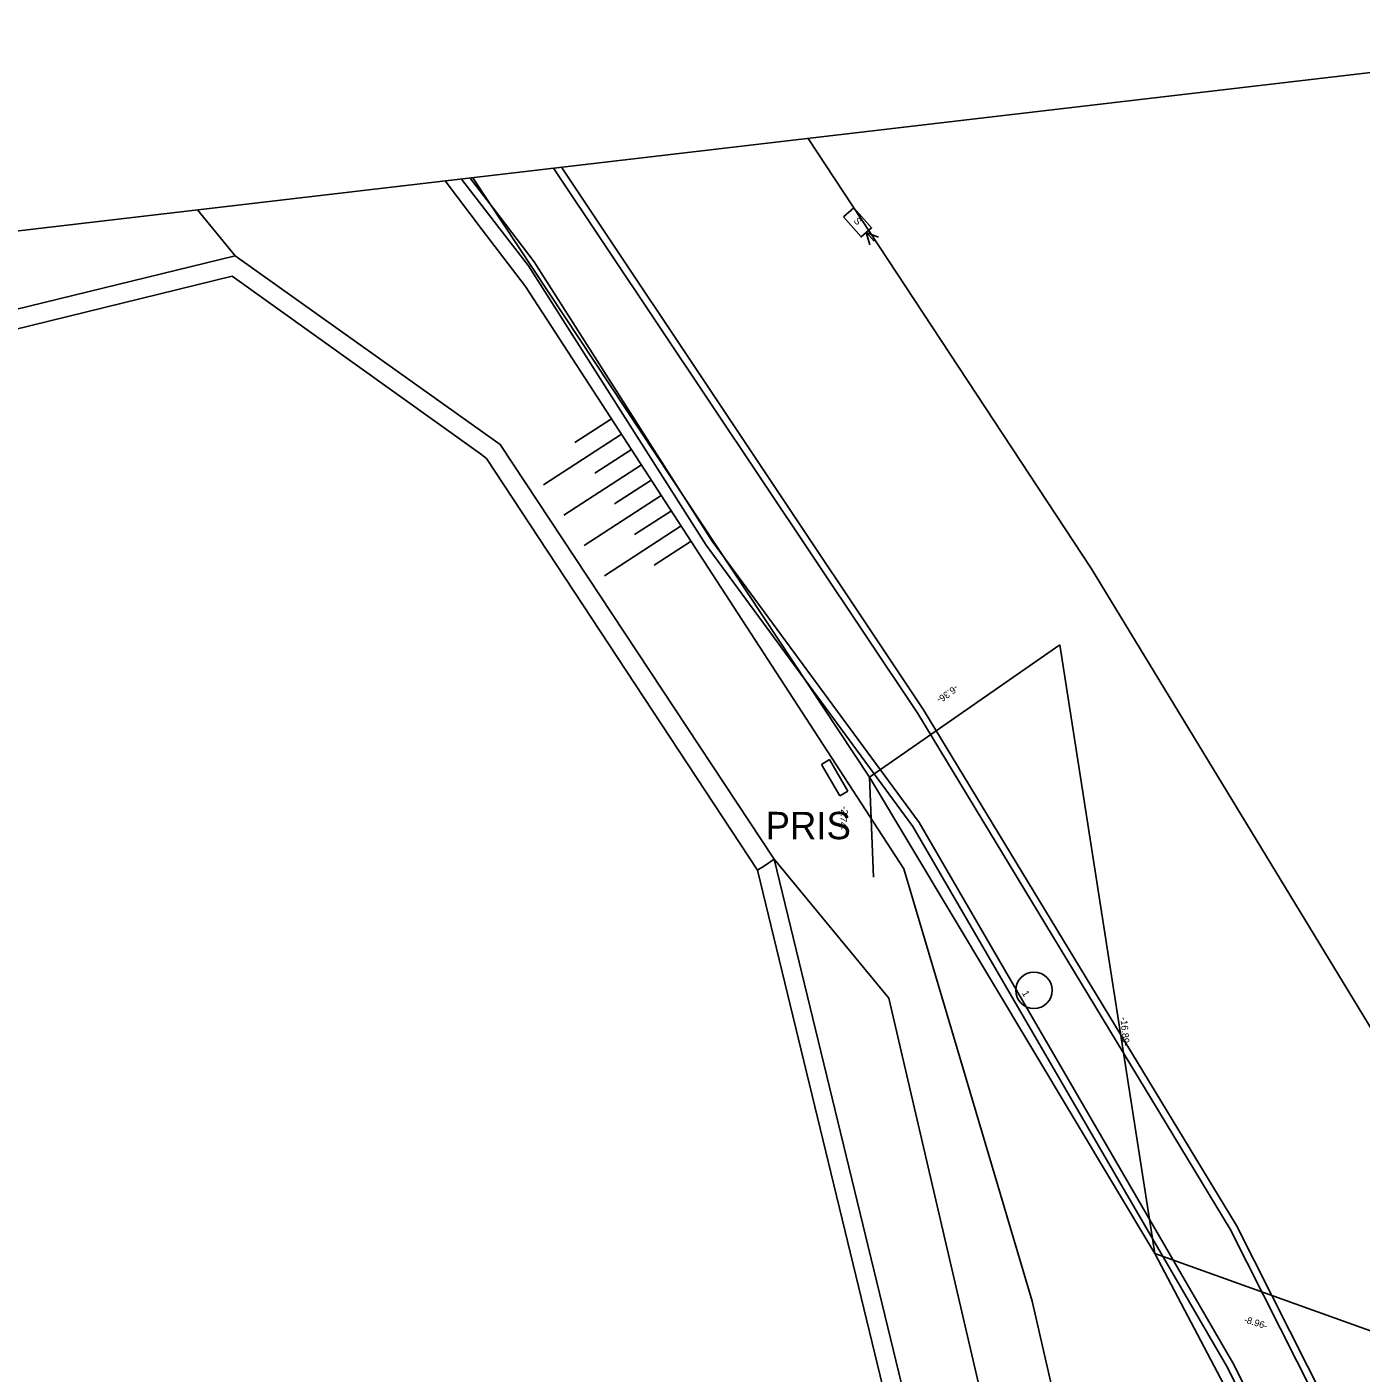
# Model space of a CAD drawing. Extents: x -597791 to -597535, y -1159670 to -1159547.
# Drawn here: x -597726 to -597689.44, y -1159583.4 to -1159546.5 of the extents above; entities that cross this region are included whole.
import ezdxf

# ---------------------------------------------------------------- set-up
doc = ezdxf.new("R2010")
doc.units = 0
for name, color, linetype in [('Koordinační kabel-Pom_KK Metalic', 7, 'Continuous'), ('Koordinační kabel-Pom_Oměrná KKM', 7, 'Continuous'), ('Koordinační kabel-Pom_Text KKM', 7, 'Continuous'), ('MAPA', 7, 'Continuous'), ('Ostatní', 7, 'Continuous'), ('Žádosti', 7, 'Continuous')]:
    doc.layers.add(name, color=color, linetype=linetype)

msp = doc.modelspace()

# ---------------------------------------------------------------- linework, layer by layer
at = {"layer": 'Koordinační kabel-Pom_KK Metalic'}
msp.add_lwpolyline([(-597673.151, -1159662.001), (-597672.53, -1159646.67), (-597673.26, -1159634.82), (-597674.43, -1159629.89), (-597674.64, -1159626.96), (-597676.13, -1159624.16), (-597682.12, -1159607.29), (-597687.7, -1159594.16), (-597695.09, -1159580.13), (-597702.91, -1159567.07), (-597713.779, -1159550.637)], dxfattribs=at)
at = {"layer": 'Koordinační kabel-Pom_Oměrná KKM'}
for points in [[(-597697.69, -1159563.44), (-597702.91, -1159567.07)], [(-597695.09, -1159580.13), (-597697.69, -1159563.44)], [(-597702.91, -1159567.07), (-597702.8, -1159569.81)], [(-597695.09, -1159580.13), (-597686.66, -1159583.15)]]:
    msp.add_lwpolyline(points, dxfattribs=at)
at = {"layer": 'Koordinační kabel-Pom_Text KKM'}
msp.add_circle((-597698.404, -1159572.911), 0.5, dxfattribs=at)
at = {"layer": 'MAPA'}
for p, q in [((-597711.569, -1159550.378), (-597701.59, -1159565.32)), ((-597721.331, -1159551.521), (-597720.29, -1159552.78))]:
    msp.add_line(p, q, dxfattribs=at)
for points in [[(-597704.593, -1159549.561), (-597696.83, -1159561.36), (-597686.72, -1159577.97), (-597680.02, -1159590.93), (-597674.28, -1159604.46), (-597669.36, -1159619.22), (-597665.99, -1159632.8), (-597665.39, -1159635.96)], [(-597711.348, -1159550.352), (-597701.43, -1159565.22), (-597692.85, -1159579.36)], [(-597714.535, -1159550.725), (-597713.521, -1159552.063), (-597712.34, -1159553.62), (-597701.97, -1159569.58), (-597698.45, -1159581.43), (-597695.48, -1159594.37), (-597692.77, -1159605.67), (-597689.38, -1159619.96), (-597686.19, -1159632.52), (-597681.76, -1159634.88), (-597680.28, -1159632.32), (-597675.87, -1159632.46)], [(-597714.094, -1159550.674), (-597713.193, -1159551.841), (-597712.26, -1159553.05), (-597707.39, -1159560.71)], [(-597713.858, -1159550.646), (-597713.03, -1159551.72), (-597712.1, -1159552.94), (-597707.22, -1159560.6)], [(-597757.7, -1159561.95), (-597747.37, -1159559.39), (-597720.29, -1159552.78), (-597713.03, -1159557.95), (-597705.52, -1159569.32)], [(-597758.88, -1159636.94), (-597772.32, -1159583.78), (-597776.69, -1159567.07), (-597747.44, -1159559.98), (-597720.38, -1159553.34), (-597713.57, -1159558.21), (-597713.41, -1159558.33), (-597705.98, -1159569.62)], [(-597710.99, -1159557.9), (-597709.98, -1159557.25)], [(-597711.84, -1159559.06), (-597709.71, -1159557.67)], [(-597710.44, -1159558.74), (-597709.43, -1159558.09)], [(-597711.29, -1159559.89), (-597709.16, -1159558.51)], [(-597709.9, -1159559.58), (-597708.89, -1159558.93)], [(-597710.73, -1159560.72), (-597708.62, -1159559.35)], [(-597709.35, -1159560.42), (-597708.34, -1159559.77)], [(-597710.17, -1159561.55), (-597708.07, -1159560.18)], [(-597708.81, -1159561.26), (-597707.8, -1159560.6)], [(-597707.22, -1159560.6), (-597701.55, -1159568.31), (-597692.95, -1159583.12), (-597688.53, -1159591.92), (-597684.81, -1159600.9)], [(-597707.39, -1159560.71), (-597701.72, -1159568.42), (-597693.13, -1159583.21), (-597688.72, -1159592.01), (-597684.99, -1159600.98)], [(-597701.59, -1159565.32), (-597693.03, -1159579.46)], [(-597704.01, -1159566.59), (-597704.23, -1159566.72)], [(-597703.5, -1159567.45), (-597704.01, -1159566.59)], [(-597704.23, -1159566.72), (-597703.72, -1159567.58)], [(-597703.72, -1159567.58), (-597703.5, -1159567.45)], [(-597705.79, -1159569.5), (-597705.98, -1159569.62)], [(-597705.52, -1159569.32), (-597705.79, -1159569.5)], [(-597694.69, -1159606.19), (-597702.38, -1159573.13), (-597705.52, -1159569.32)], [(-597689.86, -1159633.14), (-597692.53, -1159622.57), (-597699.3, -1159594.96), (-597705.52, -1159569.32)], [(-597705.98, -1159569.62), (-597699.55, -1159596.14)], [(-597693.03, -1159579.46), (-597685.25, -1159594.86)], [(-597692.85, -1159579.36), (-597685.07, -1159594.78), (-597681.9, -1159602.47)]]:
    msp.add_lwpolyline(points, dxfattribs=at)
at = {"layer": 'Ostatní'}
for points in [[(-597703.626, -1159551.713), (-597703.341, -1159551.461), (-597702.855, -1159552.01), (-597703.14, -1159552.262), (-597703.626, -1159551.713)], [(-597702.667, -1159552.271), (-597702.997, -1159552.135), (-597702.903, -1159552.481)], [(-597702.993, -1159552.141), (-597702.779, -1159552.381)]]:
    msp.add_lwpolyline(points, dxfattribs=at)
at = {"layer": 'Žádosti'}
msp.add_lwpolyline([(-597654.67, -1159660.54), (-597678.483, -1159546.504), (-597791.46, -1159559.733), (-597772.145, -1159668.212), (-597768.441, -1159669.535)], close=True, dxfattribs=at)

# ---------------------------------------------------------------- texts
at = {"layer": 'Koordinační kabel-Pom_Oměrná KKM'}
for s, rotation, p in [('-6.36-', 216.0253, (-597700.56, -1159564.525)), ('-2.74-', 263.7432, (-597703.674, -1159567.859)), ('-16.89-', 274.8375, (-597696.033, -1159573.658)), ('-8.96-', 342.8438, (-597692.665, -1159582.014))]:
    msp.add_text(s, height=0.1875, rotation=rotation, dxfattribs=at).set_placement(p)
at = {"layer": 'Koordinační kabel-Pom_Text KKM'}
msp.add_text('1', height=0.188, rotation=300.2, dxfattribs=at).set_placement((-597698.74, -1159572.989))
at = {"layer": 'MAPA'}
msp.add_text('PRIS', height=0.75, rotation=359.9882, dxfattribs=at).set_placement((-597705.76, -1159568.77))
at = {"layer": 'Ostatní'}
msp.add_text('S', height=0.188, rotation=311.5267, dxfattribs=at).set_placement((-597703.358, -1159551.827))

doc.saveas('drawing.dxf')
